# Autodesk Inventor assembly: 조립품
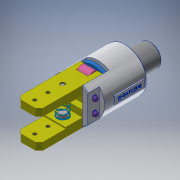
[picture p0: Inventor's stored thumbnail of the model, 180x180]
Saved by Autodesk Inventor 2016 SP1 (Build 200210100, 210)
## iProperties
Created: 2019-02
Part Number: 조립품
Material: 일반
Document SubType Name: Assembly
Designer: basic
Author: basic
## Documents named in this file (11)
- C:\Users\basic\Desktop\490208V1001\조립품.iam
- C:\Users\basic\Desktop\490208V1001\답안도면.ipt
- C:\Users\basic\Desktop\490208V1001\E-링.ipt
- C:\Users\basic\Desktop\490208V1001\O-링.ipt
- C:\Users\basic\Desktop\490208V1001\가이드핀.ipt
- C:\Users\basic\Desktop\490208V1001\부시.ipt
- C:\Users\basic\Desktop\490208V1001\스프링.ipt
- C:\Users\basic\Desktop\490208V1001\평행핀 6x28.ipt
- C:\Users\basic\Desktop\490208V1001\피스톤.ipt
- C:\Users\basic\Desktop\490208V1001\핀.ipt
- C:\Users\basic\Desktop\490208V1001\핑거.ipt
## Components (13 placed, 6 different names)
1. E-링:1
2. O-링:1
3. 가이드핀:1
4. 피스톤:1
5. 핀:1
6. 핑거:1 — 각도:1
7. O-링:2
8. 핑거:2
9. 핀:2
10. E-링:2
11. E-링:3
12. E-링:4
13. 가이드핀:2
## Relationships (1: Angle 1)
- 각도:1 [Angle]: 핑거:1
